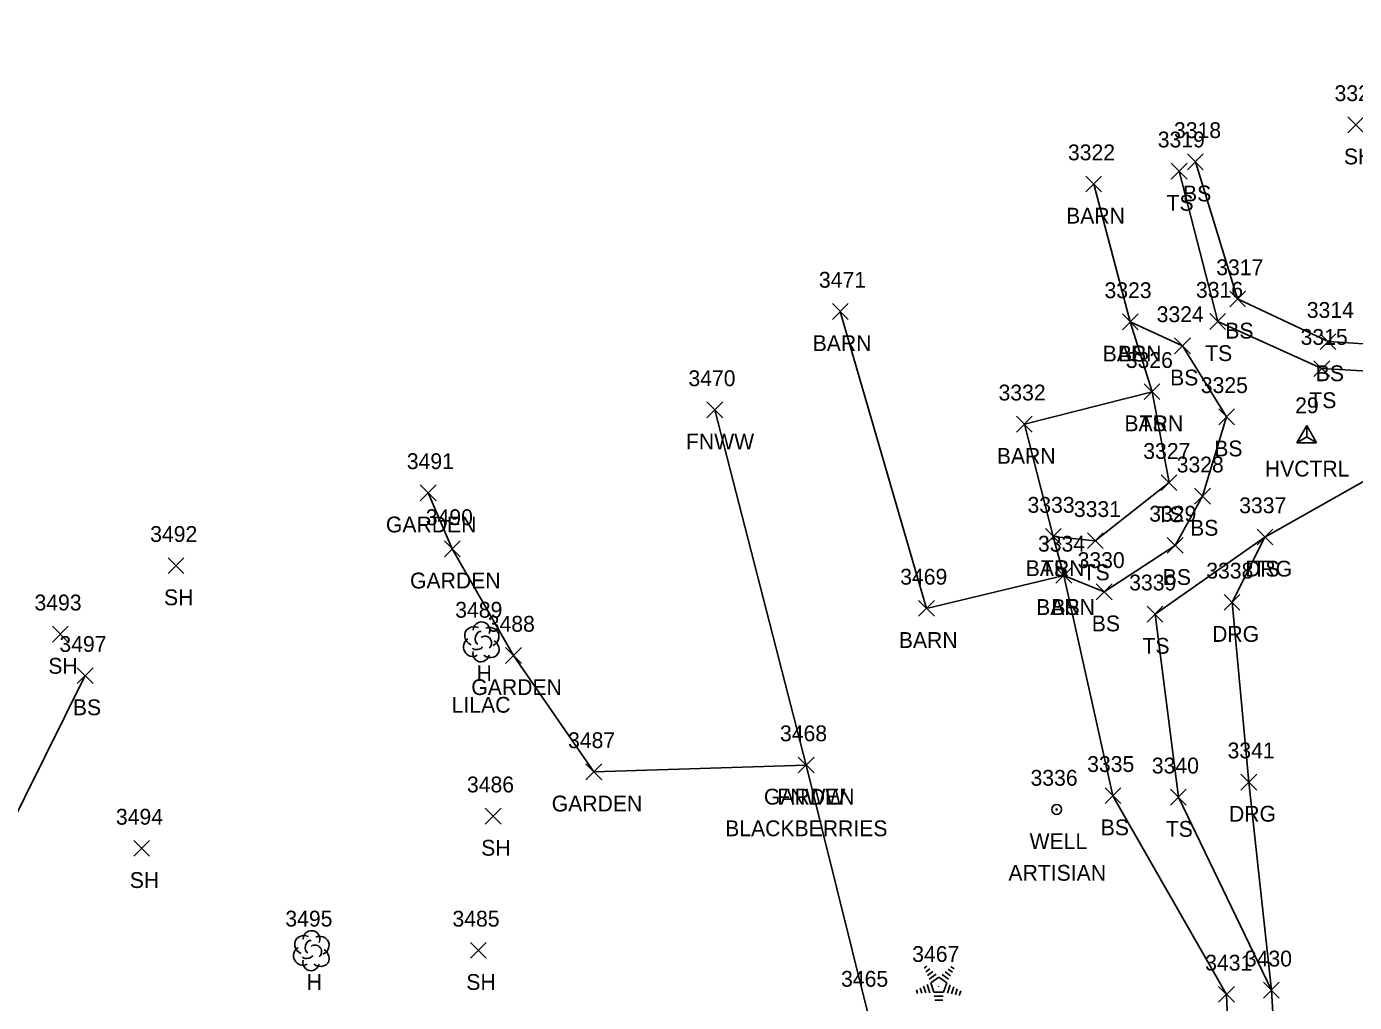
# Model space of a CAD drawing. Extents: x 1520648 to 1523413, y 732854 to 735518.
# Drawn here: x 1521541.1 to 1521708.9, y 733707.2 to 733830.5 of the extents above; entities that cross this region are included whole.
import ezdxf

# ---------------------------------------------------------------- set-up
doc = ezdxf.new("R2010")
doc.units = 0
for name, color, linetype in [('C_A', 7, 'Continuous'), ('C_I', 7, 'Continuous'), ('CPSM', 7, 'Continuous'), ('L_A', 7, 'Continuous'), ('L_C', 7, 'Continuous'), ('L_I', 7, 'Continuous'), ('L_TIC', 7, 'Continuous'), ('LAPB', 7, 'Continuous'), ('LBC', 7, 'Continuous'), ('LELB', 7, 'Continuous'), ('LFNC', 7, 'Continuous'), ('LTC', 7, 'Continuous'), ('LTD', 7, 'Continuous'), ('R_A', 7, 'Continuous'), ('R_I', 7, 'Continuous'), ('R_TIC', 7, 'Continuous'), ('RDG', 7, 'Continuous'), ('U_A', 7, 'Continuous'), ('U_C', 7, 'Continuous'), ('U_I', 7, 'Continuous'), ('UWW', 7, 'Continuous')]:
    doc.layers.add(name, color=color, linetype=linetype)

msp = doc.modelspace()

# ---------------------------------------------------------------- linework, layer by layer
at = {"layer": 'CPSM'}
for p, q in [((1521701.66, 733777.96), (1521702.91, 733780.13)), ((1521704.16, 733777.96), (1521702.91, 733780.13)), ((1521702.91, 733778.68), (1521702.91, 733780.13)), ((1521701.66, 733777.96), (1521702.91, 733778.68)), ((1521702.91, 733778.68), (1521702.91, 733778.68)), ((1521702.91, 733778.68), (1521704.16, 733777.96)), ((1521701.66, 733777.96), (1521704.16, 733777.96))]:
    msp.add_line(p, q, dxfattribs=at)
at = {"layer": 'L_TIC'}
for points in [[(1521708.11, 733817.12), (1521710.11, 733819.12)], [(1521710.11, 733817.12), (1521708.11, 733819.12)], [(1521685.78, 733811.27), (1521687.78, 733813.27)], [(1521687.78, 733811.27), (1521685.78, 733813.27)], [(1521687.83, 733812.45), (1521689.83, 733814.45)], [(1521689.83, 733812.45), (1521687.83, 733814.45)], [(1521674.99, 733809.64), (1521676.99, 733811.64)], [(1521676.99, 733809.64), (1521674.99, 733811.64)], [(1521693.17, 733795.12), (1521695.17, 733797.12)], [(1521695.17, 733795.12), (1521693.17, 733797.12)], [(1521642.96, 733793.54), (1521644.96, 733795.54)], [(1521644.96, 733793.54), (1521642.96, 733795.54)], [(1521679.61, 733792.22), (1521681.61, 733794.22)], [(1521681.61, 733792.22), (1521679.61, 733794.22)], [(1521679.61, 733792.22), (1521681.61, 733794.22)], [(1521681.61, 733792.22), (1521679.61, 733794.22)], [(1521690.66, 733792.27), (1521692.66, 733794.27)], [(1521692.66, 733792.27), (1521690.66, 733794.27)], [(1521704.6, 733789.73), (1521706.6, 733791.73)], [(1521706.6, 733789.73), (1521704.6, 733791.73)], [(1521686.2, 733789.19), (1521688.2, 733791.19)], [(1521688.2, 733789.19), (1521686.2, 733791.19)], [(1521703.82, 733786.32), (1521705.82, 733788.32)], [(1521705.82, 733786.32), (1521703.82, 733788.32)], [(1521682.36, 733783.4), (1521684.36, 733785.4)], [(1521684.36, 733783.4), (1521682.36, 733785.4)], [(1521682.36, 733783.4), (1521684.36, 733785.4)], [(1521684.36, 733783.4), (1521682.36, 733785.4)], [(1521627.11, 733781.1), (1521629.11, 733783.1)], [(1521629.11, 733781.1), (1521627.11, 733783.1)], [(1521691.78, 733780.23), (1521693.78, 733782.23)], [(1521693.78, 733780.23), (1521691.78, 733782.23)], [(1521666.22, 733779.29), (1521668.22, 733781.29)], [(1521668.22, 733779.29), (1521666.22, 733781.29)], [(1521684.51, 733771.91), (1521686.51, 733773.91)], [(1521686.51, 733771.91), (1521684.51, 733773.91)], [(1521590.87, 733770.62), (1521592.87, 733772.62)], [(1521592.87, 733770.62), (1521590.87, 733772.62)], [(1521688.73, 733770.2), (1521690.73, 733772.2)], [(1521690.73, 733770.2), (1521688.73, 733772.2)], [(1521669.88, 733765.1), (1521671.88, 733767.1)], [(1521671.88, 733765.1), (1521669.88, 733767.1)], [(1521669.88, 733765.1), (1521671.88, 733767.1)], [(1521671.88, 733765.1), (1521669.88, 733767.1)], [(1521675.18, 733764.57), (1521677.18, 733766.57)], [(1521677.18, 733764.57), (1521675.18, 733766.57)], [(1521696.63, 733765.04), (1521698.63, 733767.04)], [(1521698.63, 733765.04), (1521696.63, 733767.04)], [(1521593.93, 733763.54), (1521595.93, 733765.54)], [(1521595.93, 733763.54), (1521593.93, 733765.54)], [(1521685.27, 733763.98), (1521687.27, 733765.98)], [(1521687.27, 733763.98), (1521685.27, 733765.98)], [(1521559.01, 733761.42), (1521561.01, 733763.42)], [(1521561.01, 733761.42), (1521559.01, 733763.42)], [(1521671.2, 733760.19), (1521673.2, 733762.19)], [(1521673.2, 733760.19), (1521671.2, 733762.19)], [(1521671.2, 733760.19), (1521673.2, 733762.19)], [(1521673.2, 733760.19), (1521671.2, 733762.19)], [(1521676.3, 733758.12), (1521678.3, 733760.12)], [(1521678.3, 733758.12), (1521676.3, 733760.12)], [(1521653.85, 733756.02), (1521655.85, 733758.02)], [(1521655.85, 733756.02), (1521653.85, 733758.02)], [(1521682.74, 733755.29), (1521684.74, 733757.29)], [(1521684.74, 733755.29), (1521682.74, 733757.29)], [(1521544.39, 733752.76), (1521546.39, 733754.76)], [(1521546.39, 733752.76), (1521544.39, 733754.76)], [(1521601.67, 733750.07), (1521603.67, 733752.07)], [(1521603.67, 733750.07), (1521601.67, 733752.07)], [(1521547.54, 733747.52), (1521549.54, 733749.52)], [(1521549.54, 733747.52), (1521547.54, 733749.52)], [(1521638.64, 733736.23), (1521640.64, 733738.23)], [(1521640.64, 733736.23), (1521638.64, 733738.23)], [(1521638.64, 733736.23), (1521640.64, 733738.23)], [(1521640.64, 733736.23), (1521638.64, 733738.23)], [(1521611.82, 733735.36), (1521613.82, 733737.36)], [(1521613.82, 733735.36), (1521611.82, 733737.36)], [(1521677.42, 733732.35), (1521679.42, 733734.35)], [(1521679.42, 733732.35), (1521677.42, 733734.35)], [(1521685.68, 733732.16), (1521687.68, 733734.16)], [(1521687.68, 733732.16), (1521685.68, 733734.16)], [(1521599.09, 733729.77), (1521601.09, 733731.77)], [(1521601.09, 733729.77), (1521599.09, 733731.77)], [(1521554.68, 733725.69), (1521556.68, 733727.69)], [(1521556.68, 733725.69), (1521554.68, 733727.69)], [(1521597.21, 733712.81), (1521599.21, 733714.81)], [(1521599.21, 733712.81), (1521597.21, 733714.81)], [(1521691.76, 733707.25), (1521693.76, 733709.25)], [(1521693.76, 733707.25), (1521691.76, 733709.25)], [(1521697.44, 733707.77), (1521699.44, 733709.77)], [(1521699.44, 733707.77), (1521697.44, 733709.77)]]:
    msp.add_lwpolyline(points, dxfattribs=at)
at = {"layer": 'LAPB'}
msp.add_lwpolyline([(1521639.64, 733737.23), (1521612.82, 733736.36), (1521602.67, 733751.07), (1521594.93, 733764.54), (1521591.87, 733771.62)], dxfattribs=at)
at = {"layer": 'LBC'}
msp.add_lwpolyline([(1521675.99, 733810.64), (1521680.61, 733793.22), (1521683.36, 733784.4), (1521667.22, 733780.29), (1521670.88, 733766.1), (1521672.2, 733761.19), (1521654.85, 733757.02), (1521643.96, 733794.54)], dxfattribs=at)
at = {"layer": 'LELB'}
for points in [[(1521739.04, 733828.49), (1521741.35, 733815.87), (1521743.82, 733807.11), (1521734.29, 733792.62), (1521717.25, 733786.6), (1521704.82, 733787.32), (1521691.66, 733793.27), (1521686.78, 733812.27)], [(1521736.77, 733827.52), (1521738.69, 733815.41), (1521740.88, 733807.23), (1521732.92, 733795.46), (1521715.22, 733790.11), (1521705.6, 733790.73), (1521694.17, 733796.12), (1521688.83, 733813.45)], [(1521680.61, 733793.22), (1521687.2, 733790.19), (1521692.78, 733781.23), (1521689.73, 733771.2), (1521686.27, 733764.98), (1521677.3, 733759.12), (1521672.2, 733761.19), (1521678.42, 733733.35), (1521692.76, 733708.25), (1521693.26, 733695.59)], [(1521683.36, 733784.4), (1521685.51, 733772.91), (1521676.18, 733765.57), (1521670.88, 733766.1)], [(1521697.63, 733766.04), (1521683.74, 733756.29), (1521686.68, 733733.16), (1521698.44, 733708.77)], [(1521548.54, 733748.52), (1521530.67, 733712.6), (1521509.85, 733695.36), (1521485.57, 733682.53), (1521468.85, 733665.31), (1521458.55, 733648.55), (1521439.32, 733651.51), (1521417.73, 733673.25), (1521424.64, 733645.07), (1521433.28, 733636.36), (1521449.81, 733635.44), (1521465.25, 733627.96)]]:
    msp.add_lwpolyline(points, dxfattribs=at)
at = {"layer": 'LFNC'}
msp.add_lwpolyline([(1521655.17, 733674.88), (1521651.51, 733690.56), (1521647.37, 733706.21), (1521639.64, 733737.23), (1521628.11, 733782.1)], dxfattribs=at)
at = {"layer": 'LTC'}
for p, q in [((1521654.55, 733711.55), (1521654.9, 733711.81)), ((1521654.76, 733711.09), (1521655.29, 733711.47)), ((1521654.97, 733710.62), (1521655.67, 733711.13)), ((1521657.2, 733711.1), (1521657.88, 733710.6)), ((1521657.58, 733711.45), (1521658.12, 733711.05)), ((1521657.95, 733711.79), (1521658.37, 733711.49)), ((1521654.49, 733709.27), (1521654.76, 733708.43)), ((1521654.95, 733709.48), (1521655.28, 733708.46)), ((1521655.18, 733710.16), (1521656.06, 733710.79)), ((1521655.4, 733709.7), (1521656.41, 733710.44)), ((1521655.4, 733709.7), (1521655.79, 733708.51)), ((1521656.41, 733710.44), (1521657.41, 733709.71)), ((1521656.83, 733710.75), (1521657.64, 733710.16)), ((1521657.41, 733709.71), (1521657.02, 733708.51)), ((1521657.85, 733709.44), (1521657.51, 733708.4)), ((1521653.58, 733708.83), (1521653.73, 733708.37)), ((1521654.04, 733709.05), (1521654.25, 733708.4)), ((1521657.02, 733708.51), (1521655.79, 733708.51)), ((1521656.98, 733708.01), (1521655.84, 733708.01)), ((1521658.29, 733709.19), (1521658, 733708.31)), ((1521658.74, 733708.94), (1521658.5, 733708.21)), ((1521659.18, 733708.69), (1521658.99, 733708.12)), ((1521656.9, 733707.51), (1521655.91, 733707.51))]:
    msp.add_line(p, q, dxfattribs=at)
at = {"layer": 'LTD'}
for p, q in [((1521598.57, 733752.84), (1521598.57, 733752.84)), ((1521598.57, 733752.84), (1521598.57, 733752.84)), ((1521577.09, 733713.82), (1521577.09, 733713.82)), ((1521577.09, 733713.82), (1521577.09, 733713.82))]:
    msp.add_line(p, q, dxfattribs=at)
for centre in [(1521598.62, 733754.27), (1521577.14, 733715.25)]:
    msp.add_arc(centre, 1.05, 335.5272, 180.9563, dxfattribs=at)
for centre, major_axis, ratio, start_param, end_param in [((1521597.78, 733753.51), (1.21, -0.51), 0.895232, 1.570796, 4.712389), ((1521599.61, 733753.42), (-1.14, -0.48), 0.949671, 1.570796, 4.712389), ((1521597.49, 733752.13), (0.58, -1.04), 0.959034, 3.141593, 6.283185), ((1521598.36, 733753.3), (-0.208, -0.792), 0.645439, 3.141593, 6.283185), ((1521599.07, 733752.67), (-0.5, 0.667), 0.989748, 3.141593, 6.283185), ((1521599.57, 733752.01), (-1.09, 0.79), 0.841452, 1.570796, 4.712389), ((1521598.57, 733751.34), (0.26, 1.06), 0.942809, 1.570796, 4.712389), ((1521598.11, 733752.09), (-0.625, -0.083), 0.423636, 0, 3.141593), ((1521576.3, 733714.48), (1.21, -0.51), 0.895232, 1.570796, 4.712389), ((1521576.88, 733714.28), (-0.208, -0.792), 0.645439, 3.141593, 6.283185), ((1521577.59, 733713.65), (-0.5, 0.667), 0.989748, 3.141593, 6.283185), ((1521578.13, 733714.4), (-1.14, -0.48), 0.949671, 1.570796, 4.712389), ((1521576.01, 733713.11), (0.58, -1.04), 0.959034, 3.141593, 6.283185), ((1521577.09, 733712.32), (0.26, 1.06), 0.942809, 1.570796, 4.712389), ((1521576.63, 733713.07), (-0.625, -0.083), 0.423636, 0, 3.141593), ((1521578.09, 733712.98), (-1.09, 0.79), 0.841452, 1.570796, 4.712389)]:
    msp.add_ellipse(centre, major_axis=major_axis, ratio=ratio, start_param=start_param, end_param=end_param, dxfattribs=at)
at = {"layer": 'R_TIC'}
for points in [[(1521696.63, 733765.04), (1521698.63, 733767.04)], [(1521698.63, 733765.04), (1521696.63, 733767.04)], [(1521692.47, 733756.79), (1521694.47, 733758.79)], [(1521694.47, 733756.79), (1521692.47, 733758.79)], [(1521694.59, 733734.07), (1521696.59, 733736.07)], [(1521696.59, 733734.07), (1521694.59, 733736.07)], [(1521697.44, 733707.77), (1521699.44, 733709.77)], [(1521699.44, 733707.77), (1521697.44, 733709.77)]]:
    msp.add_lwpolyline(points, dxfattribs=at)
at = {"layer": 'RDG'}
msp.add_lwpolyline([(1521744.11, 733830.54), (1521748.35, 733816.63), (1521749.54, 733807.46), (1521738.35, 733788.14), (1521720.34, 733778.85), (1521697.63, 733766.04), (1521693.47, 733757.79), (1521695.59, 733735.07), (1521698.44, 733708.77), (1521699.35, 733693.83), (1521691.81, 733681.75), (1521685.16, 733676.19), (1521682.58, 733672.91)], dxfattribs=at)
at = {"layer": 'UWW'}
for radius in [0.625, 0.0833]:
    msp.add_circle((1521671.31, 733731.61), radius, dxfattribs=at)

# ---------------------------------------------------------------- texts
at = {"layer": 'C_A'}
msp.add_text('HVCTRL', height=2, dxfattribs=at).set_placement((1521697.61, 733773.68))
at = {"layer": 'C_I'}
msp.add_text('29', height=2, dxfattribs=at).set_placement((1521701.44, 733781.68))
at = {"layer": 'L_A'}
for s, p in [('SH', (1521707.6, 733813.12)), ('BS', (1521687.27, 733808.45)), ('TS', (1521685.19, 733807.27)), ('BARN', (1521672.5, 733805.64)), ('BS', (1521692.61, 733791.12)), ('BARN', (1521640.47, 733789.54)), ('BARN', (1521677.12, 733788.22)), ('BS', (1521679.05, 733788.22)), ('TS', (1521690.07, 733788.27)), ('BS', (1521685.64, 733785.19)), ('BS', (1521704.04, 733785.73)), ('TS', (1521703.23, 733782.32)), ('BARN', (1521679.87, 733779.4)), ('TS', (1521681.77, 733779.4)), ('FNWW', (1521624.46, 733777.1)), ('BS', (1521691.22, 733776.23)), ('BARN', (1521663.74, 733775.29)), ('TS', (1521683.92, 733767.91)), ('GARDEN', (1521586.54, 733766.62)), ('BS', (1521688.17, 733766.2)), ('BARN', (1521667.39, 733761.1)), ('TS', (1521669.29, 733761.1)), ('TS', (1521696.04, 733761.04)), ('GARDEN', (1521589.59, 733759.54)), ('TS', (1521674.59, 733760.57)), ('BS', (1521684.71, 733759.98)), ('SH', (1521558.5, 733757.42)), ('BARN', (1521668.71, 733756.19)), ('BS', (1521670.64, 733756.19)), ('BS', (1521675.74, 733754.12)), ('BARN', (1521651.36, 733752.02)), ('TS', (1521682.15, 733751.29)), ('SH', (1521543.87, 733748.76)), ('H', (1521598, 733747.84)), ('GARDEN', (1521597.33, 733746.07)), ('BS', (1521546.98, 733743.52)), ('GARDEN', (1521607.49, 733731.36)), ('GARDEN', (1521634.31, 733732.23)), ('FNWW', (1521635.99, 733732.23)), ('BS', (1521676.87, 733728.35)), ('TS', (1521685.09, 733728.16)), ('SH', (1521598.58, 733725.77)), ('SH', (1521554.17, 733721.69)), ('H', (1521576.52, 733708.82)), ('SH', (1521596.7, 733708.81))]:
    msp.add_text(s, height=2, dxfattribs=at).set_placement(p)
at = {"layer": 'L_C'}
for s, p in [('LILAC', (1521594.85, 733743.84)), ('BLACKBERRIES', (1521629.41, 733728.23))]:
    msp.add_text(s, height=2, dxfattribs=at).set_placement(p)
at = {"layer": 'L_I'}
for s, p in [('3321', (1521706.42, 733821.12)), ('3318', (1521686.13, 733816.45)), ('3319', (1521684.08, 733815.27)), ('3322', (1521672.73, 733813.64)), ('3317', (1521691.47, 733799.12)), ('3471', (1521641.26, 733797.54)), ('3323', (1521677.35, 733796.22)), ('3323', (1521677.35, 733796.22)), ('3316', (1521688.91, 733796.27)), ('3324', (1521683.94, 733793.19)), ('3314', (1521702.91, 733793.73)), ('3315', (1521702.13, 733790.32)), ('3326', (1521680.04, 733787.4)), ('3326', (1521680.04, 733787.4)), ('3470', (1521624.77, 733785.1)), ('3332', (1521663.96, 733783.29)), ('3325', (1521689.52, 733784.23)), ('3491', (1521589.18, 733774.62)), ('3327', (1521682.25, 733775.91)), ('3328', (1521686.47, 733774.2)), ('3333', (1521667.62, 733769.1)), ('3333', (1521667.62, 733769.1)), ('3331', (1521673.48, 733768.57)), ('3329', (1521683, 733767.98)), ('3337', (1521694.37, 733769.04)), ('3490', (1521591.58, 733767.54)), ('3492', (1521556.75, 733765.42)), ('3334', (1521668.94, 733764.19)), ('3334', (1521668.94, 733764.19)), ('3330', (1521673.95, 733762.12)), ('3469', (1521651.53, 733760.02)), ('3339', (1521680.47, 733759.29)), ('3493', (1521542.13, 733756.76)), ('3489', (1521595.3, 733755.84)), ('3488', (1521599.41, 733754.07)), ('3497', (1521545.28, 733751.52)), ('3487', (1521609.56, 733739.36)), ('3468', (1521636.34, 733740.23)), ('3468', (1521636.34, 733740.23)), ('3335', (1521675.16, 733736.35)), ('3340', (1521683.33, 733736.16)), ('3486', (1521596.78, 733733.77)), ('3494', (1521552.42, 733729.69)), ('3495', (1521573.83, 733716.82)), ('3485', (1521594.95, 733716.81)), ('3467', (1521653.05, 733712.35)), ('3431', (1521690.07, 733711.25)), ('3430', (1521695.09, 733711.77)), ('3465', (1521644.06, 733709.21))]:
    msp.add_text(s, height=2, dxfattribs=at).set_placement(p)
at = {"layer": 'LTC'}
msp.add_text('.', height=1.04, rotation=270, dxfattribs=at).set_placement((1521656.3, 733709.45))
at = {"layer": 'R_A'}
for p in [(1521695.12, 733761.04), (1521690.95, 733752.79), (1521693.08, 733730.07)]:
    msp.add_text('DRG', height=2, dxfattribs=at).set_placement(p)
at = {"layer": 'R_I'}
for s, p in [('3337', (1521694.37, 733769.04)), ('3338', (1521690.21, 733760.79)), ('3341', (1521692.9, 733738.07)), ('3430', (1521695.09, 733711.77))]:
    msp.add_text(s, height=2, dxfattribs=at).set_placement(p)
at = {"layer": 'U_A'}
msp.add_text('WELL', height=2, dxfattribs=at).set_placement((1521667.88, 733726.61))
at = {"layer": 'U_C'}
msp.add_text('ARTISIAN', height=2, dxfattribs=at).set_placement((1521665.21, 733722.61))
at = {"layer": 'U_I'}
msp.add_text('3336', height=2, dxfattribs=at).set_placement((1521668, 733734.61))

doc.saveas('drawing.dxf')
